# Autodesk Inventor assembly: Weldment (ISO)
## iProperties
Length Units: 11269
Angle Units: 11283
Time Units: 11279
Mass Units: 11290
Length Display Precision: 3
Angle Display Precision: 2
Part Number: Weldment (ISO)
Document SubType Name: Weldment
Created: 2002-06
Designer: smithga
Created: 2002-08
Control State: 0
Master: False
Shininess: 64.0
Angle Units: 11279
Time Units: 11290
Mass Units: 11283
Compacted: True
Density: 0.0
Volumn: 0.0
Area: 0.0
PropertySet Name: Model Information
